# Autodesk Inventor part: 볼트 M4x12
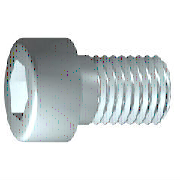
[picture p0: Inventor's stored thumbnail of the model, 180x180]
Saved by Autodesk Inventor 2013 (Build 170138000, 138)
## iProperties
IsCustomPart: 0
Created: 2012-02
Part Number: 볼트 M4x12
Material: 강철, 연강
Description: 6각머리 태핑 나사
Document SubType Name: Modeling
Standard: KS B 1003
Designer: mduedu
Standards Organization: KS
Language: ko-KR
Size Designation: M 4 x 12
Categories: <MemberInstance><Categories><Category DisplayName="조임쇠" InternalName="e4da775c-781d-43d5-af7c-5136215cf5a6" Mnemonic="FSTN"><Category DisplayName="볼트" InternalN
Density: 1 g/cm^3
Author: mduedu
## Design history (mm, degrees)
sketch "스케치1"
  geometry: L1 (-1, 0)-(12, 0); L2 (12, 0)-(12, 2); L3 (12, 2)-(1.75, 2); L4 (1.75, 2)-(1.32, 2); L5 (1.32, 2)-(0, 2); L6 (0, 2)-(0, 3.5); L7 (0, 3.5)-(-4, 3.5); L8 (-4, 3.5)-(-4, 1.732); L9 (-4, 1.732)-(-2, 1.732); L10 (-2, 1.732)-(-1, 0); L11 (-7.2, 0)-(15.2, 0) reference; L12 (0, -0.7)-(0, 4.2) reference; L13 (1.75, 2)-(0, 2)
  constraints: 22 end point, 6 parallel, 2 collinear, 2 perpendicular, 1 horizontal, 1 point on line
  dimensions: "d1" = 10.25 distance from line of L3.end L2 (= GEL); "d2" = 0.42952 distance of L4.end L3.end (computed from GAL); "d3" = 4 distance between parallel lines of L8 L6 (= KOH); "d4" = 2 distance of L8.end L9.end (= INTI); "d5" = 60 deg angle of L10 L1; "d6" = 4 diameter of L3 L1 (= GD); "d7" = 4 diameter of L5 L1 (= BDM); "d8" = 3.4641 diameter of L9 L1 (= 1.1547 x SW); "d9" = 7 diameter of L7 L1 (= KOD); "d26" = 12 distance between parallel lines of L12 L2 (= NLG)
revolve "본체" sketch "스케치1" stored, may be unused: angle "d10" = 90 deg
sketch "스케치2"
  geometry: L1 (0, -4.9)-(0, 4.9) reference; L2 (-4.9, 0)-(4.9, 0) reference; L3 (1.732, 0)-(0.866, -1.5); L4 (0.866, -1.5)-(-0.866, -1.5); L5 (-0.866, -1.5)-(-1.732, 0); L6 (-1.732, 0)-(-0.866, 1.5); L7 (-0.866, 1.5)-(0.866, 1.5); L8 (0.866, 1.5)-(1.732, 0); 2 further points
  constraints: 12 end point, 1 coincident, 1 horizontal alignment, 1 point on line, 12 other
extrude "슬롯" join sketch "스케치2" stored distance "d11" = 10; taper "d12" = 0 deg
workplane "Work Plane1"
fillet "Fillet2" dims "d30" = 0.1 (= R)
body "Solid1"
fillet "모깎기1" dims "d17" = 0.4 (= RR)
feature "스레드" dims "d13" = 10.25 (= GEL), "d14" = 0
chamfer "모따기1" distance "d15" = 0.42941 (= -0.5 x SPD + 0.5 x GD); stored, may be unused: second distance "d16" = 0.42941 (= GUL), angle "d27" = 45 deg
other parameters: "GD" = 4 (= NND) [user parameter; used in 2 equation terms], "NLG" = 12 [user parameter; used in 1 equation term], "GEL" = 10.25 [user parameter; used in 2 equation terms], "KOD" = 7 [user parameter; used in 1 equation term], "KOH" = 4 [user parameter; used in 1 equation term], "INTI" = 2 [user parameter; used in 1 equation term], "GAL" = 0.42941 (= 0.61345 x PTC) [user parameter; used in 1 equation term], "GUL" = 0.42941 (= 0.61345 x PTC) [user parameter; used in 1 equation term], "BDM" = 4 (= NND) [user parameter; used in 1 equation term], "SW" = 3 [user parameter; used in 2 equation terms], "RR" = 0.4 [user parameter; used in 1 equation term], "SPD" = 3.14117 (= NND - 1.2269 x PTC) [user parameter; used in 1 equation term], "d19" = 0, "d28" = 0, "d29" = 0, "R" = 0.1 [user parameter; used in 1 equation term], "PHH" = 0.2 [user parameter], "GD1" = 3.14117 (= THREADDIA - 1.2269 x PTC) [user parameter], "THREADDIA" = 4 [user parameter; used in 1 equation term], "FAWI" = 45 deg [user parameter], "TPU" = 14.28571 (computed from PTC) [user parameter], "PTC" = 0.7 [user parameter; used in 5 equation terms], "NND" = 4 [user parameter; used in 3 equation terms], "TOA" = 30 deg [user parameter], "E0" = 3.465 (= 1.155 x SW) [user parameter]
